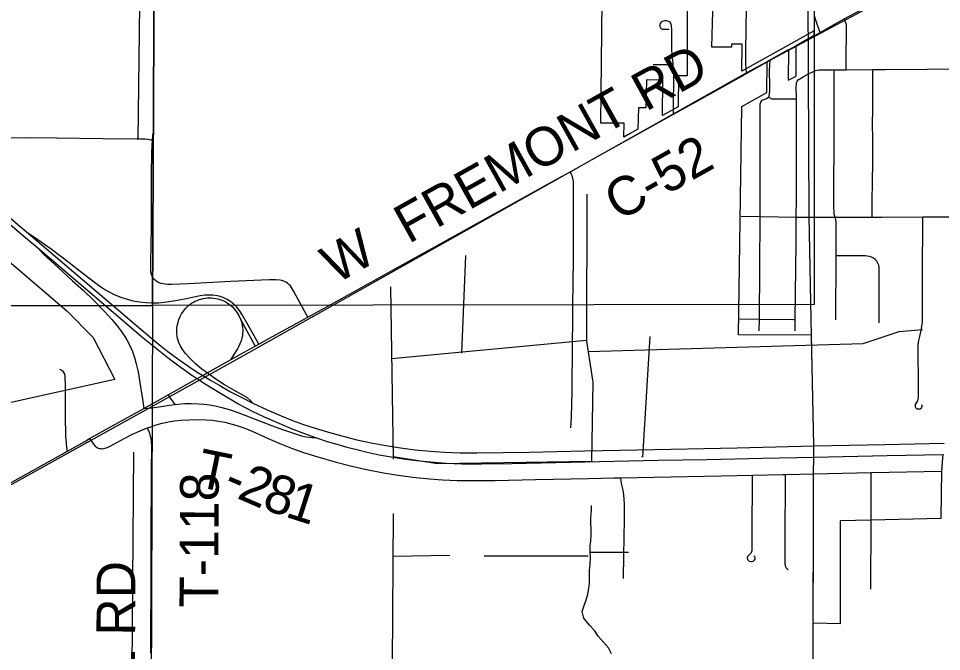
# Model space of a CAD drawing. Extents: x 0 to 34, y 0 to 22.
# Drawn here: x 2.701 to 3.379, y 17.694 to 18.159 of the extents above; entities that cross this region are included whole.
import ezdxf

# ---------------------------------------------------------------- set-up
doc = ezdxf.new("R2010")
doc.units = 0
for name, color, linetype in [('GM_X_City_Street', 7, 'Continuous'), ('GM_X_Corporation', 7, 'Continuous'), ('GM_X_County_Road', 7, 'Continuous'), ('GM_X_County_Road_Text', 7, 'Continuous'), ('GM_X_Interchange_Ramps', 7, 'Continuous'), ('GM_X_Minor_River', 7, 'Continuous'), ('GM_X_Rail_Line', 7, 'Continuous'), ('GM_X_State_Route', 7, 'Continuous'), ('GM_X_Township_Road', 7, 'Continuous'), ('GM_X_Township_Road_Text', 7, 'Continuous')]:
    doc.layers.add(name, color=color, linetype=linetype)

msp = doc.modelspace()

# ---------------------------------------------------------------- linework, layer by layer
at = {"layer": 'GM_X_City_Street'}
for points in [[(3.23613, 18.11842), (3.23582, 18.12222), (3.23557, 18.12532), (3.23549, 18.13463), (3.23611, 18.1669), (3.23611, 18.17125), (3.23607, 18.17215), (3.23594, 18.17287), (3.23521, 18.17774), (3.23497, 18.17991), (3.23485, 18.18138), (3.23476, 18.18296), (3.23473, 18.19042), (3.23478, 18.19429), (3.23484, 18.19745), (3.23507, 18.21247), (3.23519, 18.21989), (3.23538, 18.23959), (3.23551, 18.25215), (3.23563, 18.26323)], [(3.29014, 18.14844), (3.28818, 18.15395), (3.28742, 18.15593), (3.28676, 18.15813), (3.28633, 18.15984)], [(3.24548, 17.92943), (3.24554, 17.93805), (3.24608, 18.01333), (3.24614, 18.02107), (3.24616, 18.09412), (3.24621, 18.09584), (3.24654, 18.0972), (3.24703, 18.09807), (3.24763, 18.09872), (3.24915, 18.09938), (3.25073, 18.09998), (3.25197, 18.10069), (3.25242, 18.10118), (3.25271, 18.10174), (3.25296, 18.10303), (3.25312, 18.10619), (3.25313, 18.10925), (3.25307, 18.12024), (3.25324, 18.12479), (3.25337, 18.12808)], [(3.27182, 17.92948), (3.27191, 17.9378), (3.27251, 17.99412), (3.27265, 18.013), (3.27274, 18.02665), (3.27274, 18.05455), (3.27278, 18.07778), (3.27271, 18.0997), (3.27268, 18.10877), (3.27272, 18.11027), (3.27283, 18.11157), (3.27329, 18.11265), (3.27414, 18.11366), (3.27527, 18.11451), (3.27782, 18.11599)], [(3.27782, 18.11599), (3.2817, 18.11805), (3.28524, 18.11993), (3.28663, 18.12049), (3.28813, 18.12092), (3.28955, 18.12105), (3.29277, 18.12103), (3.3006, 18.12103), (3.30376, 18.12103), (3.30913, 18.12109)], [(3.30172, 17.93754), (3.30195, 17.98459), (3.30204, 18.00454), (3.3019, 18.00914), (3.30173, 18.01081), (3.30142, 18.0121), (3.30114, 18.01292), (3.30092, 18.01356), (3.3005, 18.01511), (3.30037, 18.01671), (3.30028, 18.01985), (3.3002, 18.03233), (3.30042, 18.06973), (3.30053, 18.11389), (3.30059, 18.11956), (3.3006, 18.12103)], [(3.32842, 18.01298), (3.32842, 18.01473), (3.32842, 18.01964), (3.32863, 18.04363), (3.32877, 18.04836), (3.32884, 18.06244), (3.32881, 18.07184), (3.32869, 18.07966), (3.3289, 18.09374), (3.32893, 18.11724), (3.32893, 18.1213)], [(3.25242, 18.10118), (3.25318, 18.10052), (3.25383, 18.10014), (3.25465, 18.09987), (3.26304, 18.09973), (3.27006, 18.09971), (3.27271, 18.0997)], [(3.23212, 18.01357), (3.24608, 18.01333), (3.27265, 18.013), (3.28219, 18.01297), (3.30114, 18.01292), (3.32842, 18.01298), (3.33547, 18.013), (3.36565, 18.01302), (3.38479, 18.01303)], [(3.36452, 17.87537), (3.36483, 17.87454), (3.3649, 17.87381), (3.36471, 17.87315), (3.36422, 17.87249), (3.36365, 17.87204), (3.36303, 17.87183), (3.36217, 17.87187), (3.36155, 17.87204), (3.36102, 17.87233), (3.36049, 17.87298), (3.36016, 17.87389), (3.3602, 17.87469), (3.36032, 17.8754), (3.36067, 17.87616), (3.36155, 17.87742), (3.36192, 17.87815), (3.36225, 17.87918), (3.36242, 17.88049), (3.36253, 17.88203), (3.36245, 17.89753), (3.36223, 17.90839), (3.36216, 17.91615), (3.36227, 17.91925), (3.36271, 17.92232), (3.3633, 17.92537), (3.36443, 17.92986), (3.36496, 17.93289), (3.36524, 17.93597), (3.36538, 17.94373), (3.3654, 17.97323), (3.36563, 18.0089), (3.36565, 18.01302)], [(3.33348, 17.93541), (3.33362, 17.96061), (3.33361, 17.97145), (3.33347, 17.97589), (3.33321, 17.97765), (3.33265, 17.97918), (3.33181, 17.98058), (3.3307, 17.98179), (3.3294, 17.98279), (3.32795, 17.98353), (3.32641, 17.98403), (3.32482, 17.98431), (3.32324, 17.98444), (3.32012, 17.9845), (3.3108, 17.98445), (3.30618, 17.98453), (3.30195, 17.98459)], [(3.23117, 17.93826), (3.24554, 17.93805), (3.27058, 17.93782), (3.27191, 17.9378)]]:
    msp.add_lwpolyline(points, dxfattribs=at)
at = {"layer": 'GM_X_Corporation'}
for points in [[(3.28422, 17.51924), (3.28522, 17.77692), (3.28541, 17.82472), (3.28547, 17.83697), (3.28542, 17.84529), (3.28382, 17.92584), (3.28208, 18.01325), (3.28159, 18.11833), (3.28151, 18.14407), (3.28131, 18.15363), (3.28144, 18.16526), (3.28134, 18.18409), (3.28128, 18.19949), (3.28118, 18.21462), (3.28109, 18.23015), (3.28093, 18.26402), (3.28013, 18.42718), (3.28118, 18.58272)], [(3.28422, 17.51924), (3.28522, 17.77692), (3.28541, 17.82472), (3.28547, 17.83697), (3.28542, 17.84529), (3.28382, 17.92584), (3.28208, 18.01325), (3.28159, 18.11833), (3.28151, 18.14407), (3.28131, 18.15363), (3.28144, 18.16526), (3.28134, 18.18409), (3.28128, 18.19949), (3.28118, 18.21462), (3.28109, 18.23015), (3.28093, 18.26402), (3.28013, 18.42718), (3.24639, 18.42507), (3.21893, 18.4289), (3.20161, 18.43469), (3.18477, 18.44167)], [(3.19255, 18.17295), (3.19261, 18.1166), (3.18604, 18.11674), (3.18581, 18.09378), (3.17435, 18.0874), (3.17458, 18.11353), (3.16264, 18.11364), (3.16218, 18.09305), (3.15667, 18.09309), (3.15636, 18.07743), (3.15067, 18.0742), (3.14599, 18.0716), (3.14612, 18.08194), (3.129, 18.08199), (3.13012, 18.17127)], [(3.38034, 17.839), (3.37927, 17.82661), (3.37888, 17.79155), (3.32749, 17.79048), (3.32747, 17.79048), (3.30477, 17.79), (3.30477, 17.71434), (3.28498, 17.71479), (3.28529, 17.7896), (3.28541, 17.82472), (3.28547, 17.83697), (3.28542, 17.84529), (3.28381, 17.9263), (3.23019, 17.92653), (3.23256, 18.09412), (3.25106, 18.10452), (3.25117, 18.12717), (3.26682, 18.13595), (3.26663, 18.11344), (3.27246, 18.11632), (3.27246, 18.13898), (3.28575, 18.14639), (3.2858, 18.14971), (3.23272, 18.12014), (3.23284, 18.13982), (3.22509, 18.13994), (3.22505, 18.13763), (3.21062, 18.13779), (3.21156, 18.17322)]]:
    msp.add_lwpolyline(points, dxfattribs=at)
for points in [[(2.29081, 18.44969), (2.80234, 18.44894), (2.79974, 17.94803), (2.29863, 17.94779)], [(2.80234, 18.44894), (3.28564, 18.44812), (3.28569, 17.94871), (2.79974, 17.94803)], [(2.79974, 17.94803), (2.79816, 17.44485), (2.29652, 17.45028), (2.29863, 17.94779)]]:
    msp.add_lwpolyline(points, close=True, dxfattribs=at)
at = {"layer": 'GM_X_County_Road'}
for p, q in [((3.28629, 18.14634), (3.29014, 18.14844)), ((3.26692, 18.13566), (3.27285, 18.13896)), ((3.23613, 18.11842), (3.25121, 18.12687)), ((3.25121, 18.12687), (3.25337, 18.12808)), ((3.30913, 18.12109), (3.32893, 18.1213)), ((2.87793, 17.91961), (2.88579, 17.92396))]:
    msp.add_line(p, q, dxfattribs=at)
for points in [[(3.30787, 18.15844), (3.32079, 18.16545), (3.34058, 18.17662)], [(3.29014, 18.14844), (3.30181, 18.15515), (3.30787, 18.15844)], [(3.30787, 18.15844), (3.30841, 18.15704), (3.30888, 18.15579), (3.30912, 18.15494), (3.30917, 18.154), (3.30913, 18.12442), (3.30913, 18.12109)], [(3.27285, 18.13896), (3.27696, 18.14125), (3.28162, 18.14379), (3.28586, 18.14611), (3.28629, 18.14634)], [(3.25337, 18.12808), (3.26464, 18.13439), (3.26692, 18.13566)], [(3.32893, 18.1213), (3.33781, 18.1214), (3.36897, 18.12165), (3.38922, 18.12186), (3.41367, 18.12208)], [(3.18257, 18.08849), (3.19943, 18.09787), (3.23268, 18.11649)], [(3.23268, 18.11649), (3.23335, 18.11686), (3.23613, 18.11842)], [(3.1067, 18.04624), (3.12738, 18.05785), (3.13556, 18.06233), (3.18257, 18.08849)], [(2.91379, 17.93944), (2.93837, 17.95294), (2.98592, 17.97944), (3.00501, 17.98991), (3.10026, 18.04263), (3.1067, 18.04624)], [(2.88579, 17.92396), (2.91111, 17.93797), (2.91379, 17.93944)]]:
    msp.add_lwpolyline(points, dxfattribs=at)
at = {"layer": 'GM_X_Interchange_Ramps'}
msp.add_line((2.86443, 17.93794), (2.87532, 17.91818), dxfattribs=at)
for points in [[(2.87793, 17.91961), (2.86996, 17.93348), (2.86537, 17.94162), (2.86371, 17.94425), (2.8618, 17.94671), (2.85962, 17.94893), (2.8572, 17.95088), (2.85457, 17.95253), (2.85174, 17.95385), (2.84879, 17.95481), (2.84727, 17.95517), (2.84419, 17.95561), (2.84108, 17.95572), (2.83798, 17.95553), (2.8349, 17.95511), (2.82573, 17.95327), (2.81809, 17.95173), (2.8104, 17.95048), (2.80421, 17.94983), (2.79954, 17.94969), (2.79487, 17.94988), (2.79024, 17.95042), (2.78566, 17.95132), (2.78143, 17.95234), (2.77673, 17.9539), (2.77236, 17.95572), (2.76816, 17.95775), (2.76412, 17.9601), (2.76024, 17.96269), (2.75397, 17.96726), (2.74666, 17.97289), (2.73862, 17.97926), (2.72547, 17.98938), (2.71315, 17.99804), (2.70884, 18.00091)], [(2.71553, 17.99031), (2.71942, 17.98594), (2.73101, 17.97539), (2.74099, 17.96623), (2.74912, 17.95892), (2.75702, 17.95135), (2.76467, 17.94354), (2.76996, 17.93778), (2.77397, 17.93299), (2.77681, 17.92925), (2.77944, 17.92538), (2.78106, 17.92271), (2.78323, 17.91855), (2.78507, 17.91425), (2.78663, 17.90983), (2.78791, 17.90532), (2.78922, 17.89922), (2.79123, 17.88688), (2.7924, 17.87915), (2.7934, 17.87251)], [(2.87342, 17.87642), (2.87187, 17.87836), (2.86954, 17.8802), (2.86614, 17.88214), (2.8595, 17.88594), (2.85279, 17.8898), (2.84624, 17.89394), (2.83995, 17.89849), (2.83615, 17.90121), (2.83138, 17.9052), (2.827, 17.90954), (2.82388, 17.913), (2.82203, 17.91547), (2.82044, 17.91813), (2.81919, 17.92096), (2.81869, 17.92243), (2.81829, 17.92392), (2.81798, 17.92543), (2.81778, 17.92697), (2.81768, 17.92851), (2.81768, 17.93006), (2.81779, 17.9316), (2.81799, 17.93314), (2.8183, 17.93466), (2.81918, 17.93763), (2.82042, 17.94047), (2.82116, 17.94183), (2.82199, 17.94314), (2.82388, 17.94559), (2.82494, 17.94672), (2.82608, 17.94777), (2.82728, 17.94875), (2.82855, 17.94963), (2.82987, 17.95044), (2.83124, 17.95116), (2.83266, 17.95179), (2.83411, 17.95233), (2.8356, 17.95279), (2.8371, 17.95315), (2.83863, 17.95341), (2.84017, 17.95358), (2.84172, 17.95365), (2.84327, 17.95363), (2.84481, 17.9535), (2.84634, 17.95326), (2.84785, 17.95293), (2.84934, 17.9525), (2.85079, 17.95197), (2.85221, 17.95135), (2.85359, 17.95064), (2.85492, 17.94985), (2.85619, 17.94896), (2.85741, 17.948), (2.85856, 17.94697), (2.86062, 17.94467), (2.86154, 17.94342), (2.86314, 17.94077), (2.86443, 17.93794), (2.86508, 17.93607), (2.86539, 17.935), (2.86596, 17.93196), (2.86609, 17.93042), (2.8661, 17.92888), (2.86601, 17.92733), (2.86581, 17.9258), (2.86549, 17.92428), (2.86508, 17.92279), (2.86398, 17.91989), (2.86316, 17.91815), (2.86215, 17.91612), (2.86088, 17.91397), (2.8588, 17.91073), (2.85716, 17.90812)], [(2.81121, 17.88246), (2.81282, 17.88006), (2.81444, 17.87777), (2.81628, 17.87544)]]:
    msp.add_lwpolyline(points, dxfattribs=at)
at = {"layer": 'GM_X_Minor_River'}
for points in [[(2.79195, 18.3081), (2.78894, 18.06971)], [(2.36701, 18.26457), (2.64872, 18.02059), (2.66169, 18.00811), (2.737, 17.94422), (2.75628, 17.92455), (2.77219, 17.89365), (2.65804, 17.86859), (2.54682, 17.86408), (2.47603, 17.86127), (2.42061, 17.8593)], [(3.1187, 18.02984), (3.11868, 17.92189)], [(3.02959, 17.98476), (3.02685, 17.91309)], [(2.97458, 17.96169), (2.97656, 17.83532)], [(3.11982, 17.91426), (3.32181, 17.92019), (3.34815, 17.92906), (3.36541, 17.93047)], [(3.16504, 17.92527), (3.15969, 17.83669), (3.1594, 17.83748)], [(2.97541, 17.90906), (3.11868, 17.92265)], [(3.11868, 17.92189), (3.1232, 17.89169), (3.12236, 17.83353), (3.00904, 17.83186), (2.97654, 17.83684)], [(2.78337, 17.49061), (2.78613, 17.84031)], [(3.13694, 17.6924), (3.13483, 17.69676), (3.13101, 17.70092), (3.1272, 17.70527), (3.12452, 17.70944), (3.12089, 17.71323), (3.11669, 17.71853), (3.11533, 17.72346), (3.11683, 17.72784), (3.11833, 17.73203), (3.11963, 17.73622), (3.12037, 17.74021), (3.12073, 17.7442), (3.12068, 17.75352), (3.12123, 17.75846), (3.12158, 17.76283), (3.12137, 17.76739), (3.12135, 17.77138), (3.12171, 17.77519), (3.12188, 17.77918), (3.12181, 17.79267), (3.12217, 17.79742), (3.12234, 17.80122)], [(2.97598, 17.68485), (2.97677, 17.79541)], [(2.97654, 17.76404), (3.01831, 17.76481)], [(3.04337, 17.76436), (3.11987, 17.76434)], [(3.1214, 17.76687), (3.14947, 17.76695)]]:
    msp.add_lwpolyline(points, dxfattribs=at)
at = {"layer": 'GM_X_Rail_Line'}
msp.add_lwpolyline([(2.1, 17.69647), (2.47706, 17.6952), (2.85936, 17.9071), (3.23675, 18.11922), (3.41122, 18.21266), (3.46168, 18.21534), (3.59943, 18.21743), (3.7892, 18.21812), (3.84959, 18.21709), (3.86607, 18.21571), (3.87121, 18.22086), (3.87465, 18.2267), (3.88206, 18.23221)], dxfattribs=at)
at = {"layer": 'GM_X_State_Route'}
msp.add_line((2.73729, 17.84118), (2.75005, 17.8483), dxfattribs=at)
for points in [[(2.32715, 18.32565), (2.4035, 18.2607), (2.44374, 18.22642), (2.60957, 18.08537), (2.64991, 18.0512), (2.66881, 18.03502), (2.69927, 18.00908), (2.70884, 18.00091), (2.79294, 17.92908), (2.8025, 17.92113), (2.81117, 17.91424), (2.81841, 17.9089), (2.82651, 17.90318), (2.83267, 17.89916), (2.83668, 17.89664), (2.84237, 17.89321), (2.84916, 17.88924), (2.8572, 17.88476), (2.86534, 17.88048), (2.87342, 17.87642)], [(2.32427, 18.32289), (2.43302, 18.23041), (2.53238, 18.14581), (2.5762, 18.10862), (2.6425, 18.05228), (2.67326, 18.0261), (2.70357, 18.00047), (2.71553, 17.99031), (2.75061, 17.96052), (2.79287, 17.92439), (2.80271, 17.91643), (2.81262, 17.90855), (2.82077, 17.90255), (2.82865, 17.89695)], [(2.7934, 17.87251), (2.81121, 17.88246), (2.83257, 17.89435), (2.83668, 17.89664), (2.83995, 17.89849), (2.85716, 17.90812), (2.86725, 17.91376), (2.87532, 17.91818), (2.87793, 17.91961)], [(2.82865, 17.89695), (2.82944, 17.89639), (2.83257, 17.89435), (2.8381, 17.8907), (2.84968, 17.88361), (2.86239, 17.8761), (2.86284, 17.87586)], [(2.75005, 17.8483), (2.75357, 17.85027), (2.7934, 17.87251)], [(2.7934, 17.87251), (2.79929, 17.87302), (2.80779, 17.87415), (2.81214, 17.87486), (2.81628, 17.87544), (2.81839, 17.87569), (2.82357, 17.87604), (2.8282, 17.87616), (2.83376, 17.87593), (2.83758, 17.87555), (2.84187, 17.8751), (2.84593, 17.87434), (2.85082, 17.87322), (2.85617, 17.87163), (2.85971, 17.87051), (2.86325, 17.86923), (2.88726, 17.86005), (2.89611, 17.85683), (2.90918, 17.85234), (2.91244, 17.85156), (2.91474, 17.85129), (2.91696, 17.85109), (2.91951, 17.8511)], [(2.86284, 17.87586), (2.87308, 17.87051), (2.88195, 17.86624), (2.89082, 17.86227), (2.90168, 17.85778), (2.91068, 17.8543), (2.91951, 17.8511)], [(2.87342, 17.87642), (2.88398, 17.87151), (2.89438, 17.86701), (2.90272, 17.86372), (2.91084, 17.86078), (2.91917, 17.85799), (2.92897, 17.85494), (2.93891, 17.85225), (2.94987, 17.84951), (2.96052, 17.84721), (2.97124, 17.8452), (2.98201, 17.84347), (2.99282, 17.84206), (3.00368, 17.841), (3.01456, 17.84028), (3.02545, 17.83988), (3.03791, 17.8398), (3.07681, 17.84044), (3.11725, 17.84136), (3.15614, 17.84204), (3.22925, 17.8436), (3.28553, 17.84501), (3.33783, 17.84593), (3.38129, 17.84693)], [(2.91951, 17.8511), (2.92814, 17.84826), (2.93513, 17.84617), (2.94254, 17.84409), (2.94978, 17.84219), (2.95739, 17.84033), (2.96624, 17.8385), (2.97501, 17.83691), (2.98394, 17.83558), (2.99363, 17.83433), (3.00401, 17.83316), (3.01549, 17.83222), (3.02695, 17.83183), (3.04148, 17.83171), (3.06361, 17.83202), (3.17113, 17.83444), (3.20693, 17.83508), (3.24775, 17.83592), (3.28558, 17.8367)], [(2.1, 17.48893), (2.12898, 17.50491), (2.16027, 17.52222), (2.18615, 17.53647), (2.24061, 17.56653), (2.28412, 17.59031), (2.29101, 17.59395), (2.29509, 17.59622), (2.32637, 17.61356), (2.37408, 17.63972), (2.42046, 17.66512), (2.45681, 17.68486), (2.46134, 17.68732), (2.47262, 17.6936), (2.50345, 17.71077), (2.53322, 17.72729), (2.54335, 17.73295), (2.59987, 17.76453), (2.62294, 17.77744), (2.66088, 17.79858), (2.68128, 17.80989), (2.73729, 17.84118)], [(3.28558, 17.8367), (3.33937, 17.83779), (3.38051, 17.83872)]]:
    msp.add_lwpolyline(points, dxfattribs=at)
at = {"layer": 'GM_X_Township_Road'}
for p, q in [((3.28552, 17.82444), (3.32767, 17.82532)), ((3.32748, 17.73968), (3.3276, 17.7902))]:
    msp.add_line(p, q, dxfattribs=at)
for points in [[(3.18224, 18.12499), (3.18211, 18.12639), (3.18151, 18.13104), (3.18123, 18.13726), (3.18128, 18.15001), (3.1812, 18.15127), (3.18111, 18.1525), (3.18098, 18.15363), (3.18085, 18.15437), (3.18056, 18.15509), (3.18014, 18.15574), (3.17968, 18.1562), (3.17891, 18.15663), (3.1782, 18.15686), (3.17742, 18.15696), (3.17592, 18.15696), (3.17491, 18.15683), (3.17432, 18.15664), (3.17371, 18.15635), (3.17306, 18.15578), (3.17263, 18.15503), (3.17242, 18.1543), (3.17238, 18.15361), (3.17246, 18.15276), (3.17261, 18.15229), (3.17285, 18.15188), (3.17314, 18.15153), (3.1736, 18.15122), (3.17417, 18.15102), (3.17476, 18.15093), (3.17926, 18.15089)], [(2.67801, 18.14937), (2.67813, 18.12646), (2.6784, 18.11246), (2.67817, 18.09077), (2.67786, 18.08302), (2.67774, 18.07625), (2.67782, 18.07529), (2.67795, 18.07447), (2.6782, 18.07365), (2.67866, 18.07291), (2.67947, 18.07216), (2.68062, 18.07158), (2.68183, 18.07124), (2.68301, 18.07109), (2.68425, 18.07101), (2.69599, 18.07124), (2.70926, 18.07126), (2.72936, 18.07108), (2.76342, 18.07073), (2.79111, 18.07034), (2.79445, 18.07028), (2.79649, 18.07008), (2.79895, 18.06973), (2.79985, 18.0696)], [(3.16763, 18.12493), (3.18033, 18.12498), (3.18224, 18.12499)], [(3.18257, 18.08849), (3.18254, 18.09054), (3.18247, 18.09563), (3.18272, 18.11395), (3.18252, 18.12174), (3.18224, 18.12499)], [(2.79985, 18.0696), (2.79987, 18.06994), (2.80026, 18.07449)], [(2.79868, 17.98328), (2.79878, 17.98876), (2.79907, 18.00904), (2.79897, 18.0433), (2.79939, 18.0608), (2.79985, 18.0696)], [(3.10717, 17.85833), (3.10765, 17.86609), (3.10805, 17.88474), (3.10835, 17.92049), (3.10858, 17.93603), (3.10854, 17.94691), (3.10863, 17.95002), (3.1088, 17.96245), (3.10891, 17.98422), (3.10891, 17.99665), (3.10899, 18.03396), (3.10893, 18.039), (3.10876, 18.04035), (3.10853, 18.04146), (3.108, 18.04327), (3.10736, 18.04474), (3.1067, 18.04624)], [(2.91379, 17.93944), (2.91142, 17.94384), (2.90829, 17.94967), (2.90537, 17.95507), (2.90354, 17.95842), (2.90191, 17.96123), (2.90106, 17.96237), (2.90001, 17.96345), (2.89887, 17.9644), (2.89764, 17.96521), (2.89627, 17.96584), (2.89482, 17.96632), (2.89328, 17.96661), (2.89016, 17.96687), (2.88549, 17.96686), (2.85745, 17.96558), (2.82631, 17.96393), (2.81384, 17.96348), (2.81072, 17.96354), (2.80916, 17.96366), (2.80761, 17.96389), (2.8061, 17.96424), (2.80462, 17.96475), (2.80322, 17.96545), (2.80195, 17.96635), (2.80085, 17.96743), (2.80001, 17.96872), (2.79937, 17.97014), (2.79894, 17.97164), (2.79868, 17.97318), (2.79855, 17.9763), (2.79868, 17.98328)], [(2.73729, 17.84118), (2.73697, 17.8437), (2.73657, 17.84686), (2.73622, 17.85198), (2.73598, 17.86703), (2.73592, 17.89036), (2.73574, 17.89503), (2.73556, 17.89656), (2.73518, 17.89803), (2.73441, 17.89933), (2.7332, 17.90031), (2.73179, 17.90096)], [(2.80818, 17.86188), (2.81135, 17.86259), (2.81592, 17.86335), (2.82053, 17.86384), (2.82671, 17.86421), (2.8329, 17.86432), (2.83909, 17.86412), (2.84371, 17.86374), (2.84831, 17.86313), (2.85287, 17.86231), (2.85738, 17.86125), (2.86184, 17.85997), (2.86767, 17.8579), (2.8734, 17.85555), (2.88472, 17.85043), (2.89329, 17.84674), (2.90198, 17.84333), (2.91077, 17.84019), (2.92115, 17.83688), (2.93459, 17.83299), (2.94514, 17.83028), (2.95576, 17.82788), (2.9695, 17.82521), (2.98025, 17.82346), (2.99105, 17.82208), (3.00342, 17.82081), (3.01274, 17.82013), (3.02361, 17.81965), (3.03605, 17.81944), (3.0516, 17.81956), (3.08111, 17.82021), (3.11993, 17.82093), (3.13858, 17.82139), (3.14382, 17.8215)], [(2.75357, 17.85027), (2.75544, 17.84766), (2.75654, 17.84612), (2.7577, 17.84483), (2.75919, 17.84372), (2.75991, 17.84334), (2.76077, 17.8431), (2.76188, 17.84296), (2.76255, 17.84291), (2.76404, 17.8431), (2.76567, 17.84355), (2.76718, 17.84409), (2.76863, 17.84473), (2.77957, 17.85075), (2.78508, 17.85357), (2.79073, 17.8561), (2.79423, 17.85751), (2.79613, 17.85819)], [(2.79613, 17.85819), (2.79854, 17.85907), (2.80257, 17.86036), (2.80683, 17.86158), (2.80818, 17.86188)], [(2.7985, 17.69278), (2.79853, 17.70177), (2.79885, 17.74835), (2.79886, 17.77475), (2.7992, 17.82599), (2.79926, 17.84464), (2.7991, 17.84777), (2.79875, 17.85049), (2.79846, 17.85193), (2.79815, 17.85303), (2.79783, 17.85418), (2.7975, 17.85504), (2.79717, 17.85586), (2.79641, 17.85757), (2.79613, 17.85819)], [(3.24054, 17.82348), (3.26283, 17.82393), (3.26479, 17.82398)], [(3.26666, 17.75398), (3.26607, 17.75447), (3.26563, 17.75493), (3.26518, 17.75552), (3.26493, 17.75605), (3.26474, 17.7566), (3.26463, 17.75747), (3.26457, 17.75819), (3.26451, 17.75918), (3.26448, 17.76119), (3.26445, 17.76452), (3.26459, 17.77665), (3.26478, 17.82126), (3.26479, 17.82398)], [(3.26479, 17.82398), (3.27526, 17.82426), (3.28552, 17.82444)], [(3.3276, 17.7902), (3.32768, 17.82444), (3.32767, 17.82532)], [(3.32767, 17.82532), (3.32819, 17.82533), (3.37938, 17.82633)], [(3.14382, 17.8215), (3.16808, 17.822), (3.21779, 17.82302), (3.24054, 17.82348)], [(3.14582, 17.74762), (3.1461, 17.76461), (3.14637, 17.79089), (3.14644, 17.80172), (3.14627, 17.80635), (3.14577, 17.81096), (3.14528, 17.81352), (3.14472, 17.81543), (3.14427, 17.81723), (3.14393, 17.81937), (3.14382, 17.8215)], [(3.24152, 17.76416), (3.24197, 17.76361), (3.24218, 17.76299), (3.24218, 17.76239), (3.2421, 17.76185), (3.2418, 17.76118), (3.24134, 17.76051), (3.24063, 17.76004), (3.24004, 17.75992), (3.23917, 17.75993), (3.23836, 17.76017), (3.2378, 17.76057), (3.23718, 17.76122), (3.23694, 17.76178), (3.23681, 17.76252), (3.23686, 17.7632), (3.23706, 17.76391), (3.23758, 17.76452), (3.23869, 17.76564), (3.23967, 17.76678), (3.23986, 17.76703), (3.24008, 17.76743), (3.24026, 17.7681), (3.2403, 17.76874), (3.24029, 17.76953), (3.2403, 17.77119), (3.24023, 17.77735), (3.24034, 17.78193), (3.24052, 17.82038), (3.24054, 17.82348)]]:
    msp.add_lwpolyline(points, dxfattribs=at)

# ---------------------------------------------------------------- texts
at = {"layer": 'GM_X_County_Road_Text'}
for s, height, rotation, p in [('RD', 0.028409, 28.72633, (3.16212, 18.0901)), ('FREMONT', 0.028409, 29.17527, (2.98788, 17.99298)), ('C-52', 0.028409, 29.28288, (3.14231, 18.00948)), ('W', 0.02841, 29.47552, (2.93447, 17.96334))]:
    msp.add_text(s, height=height, rotation=rotation, dxfattribs=at).set_placement(p)
at = {"layer": 'GM_X_Township_Road_Text'}
for s, height, rotation, p in [('T', 0.02841, 348.44044, (2.83096, 17.8153)), ('2', 0.02841, 336.64118, (2.86102, 17.8069)), ('T-118', 0.028409, 89.71985, (2.84802, 17.72608)), ('8', 0.02841, 341.11112, (2.87934, 17.79909)), ('-', 0.02841, 336.75324, (2.85032, 17.81149)), ('1', 0.02841, 342.17318, (2.89645, 17.79324)), ('W WONNELL RD', 0.0284091, 89.91174, (2.7867, 17.46073))]:
    msp.add_text(s, height=height, rotation=rotation, dxfattribs=at).set_placement(p)

doc.saveas('drawing.dxf')
